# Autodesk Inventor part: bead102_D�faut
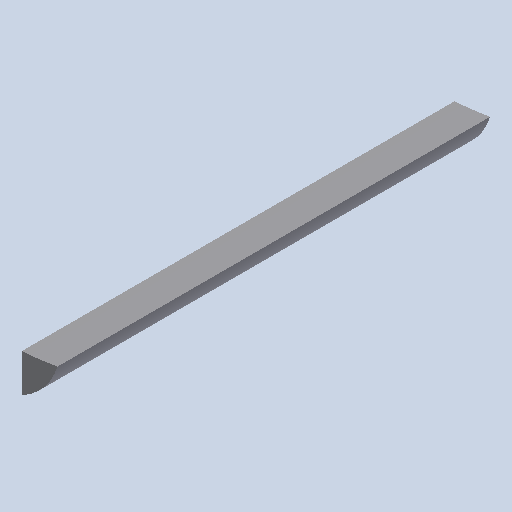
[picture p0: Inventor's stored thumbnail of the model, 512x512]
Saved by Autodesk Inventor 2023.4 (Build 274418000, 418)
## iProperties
Created: 2011-01
Part Number: bead102_D�faut
Document SubType Name: Modeling
Designer: eric
Density: 1 g/cm^3
Mass: 0.0372087 g
Surface Area: 1.24881 cm^2
Volume: 0.0372087 cm^3
Material: Générique
Appearance: Par défaut
Author: eric
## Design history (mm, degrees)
feature "Base1"
node "Corps solides"
node "Corps surfaciques"
node "Solide1"
